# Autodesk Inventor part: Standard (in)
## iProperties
Part Number: Standard (in)
Document SubType Name: Modeling
Created: 2002-08
Density: 1 g/cm^3
Control State: 0
Master: False
Checked Out: False
Shininess: 64.0
Length Units: 11272
Angle Units: 11279
Time Units: 11290
Mass Units: 11286
Length Display Precision: 3
Angle Display Precision: 2
Compacted: True
Density: 0.0
Volumn: 0.0
Area: 0.0
PropertySet Name: Model Information
